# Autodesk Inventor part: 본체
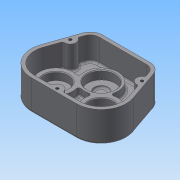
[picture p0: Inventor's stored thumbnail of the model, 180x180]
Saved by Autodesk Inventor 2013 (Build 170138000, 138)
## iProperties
Created: 2014-12
Part Number: 본체
Material: 일반
Document SubType Name: Modeling
Designer: Administrator
Density: 1 g/cm^3
Author: Administrator
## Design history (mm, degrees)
sketch "스케치1"
  geometry: L1 (0, 0)-(-32.527, -32.527); L2 (0, 0)-(32.527, -32.527); L3 (0, 0)-(0, -46); L4 (-47, 36)-(47, 36); L5 (-32.527, -68.527)-(32.527, -68.527); L6 (-66.565, -20.803)-(-47, 36); L7 (66.565, -20.803)-(47, 36); A1 r 46 centre (0, 0) between (-32.527, -32.527) and (0, -46); A2 r 36 centre (32.527, -32.527) between (32.527, -68.527) and (66.565, -20.803); A3 r 36 centre (32.527, -32.527) between (-0.86, -45.992) and (0, -47.954); A4 r 36 centre (-32.527, -32.527) between (0, -47.954) and (0.86, -45.992); A5 r 36 centre (-32.527, -32.527) between (-66.565, -20.803) and (-32.527, -68.527); 3 further points
  constraints: 14 end point, 13 point on circle, 5 centre point, 3 coincident, 2 midpoint, 2 tangent, 2 vertical alignment, 1 parallel, 1 perpendicular, 1 vertical
  dimensions: "d2" = 92 diameter of A1; "d3" = 45 deg angle of L3 L1; "d5" = 45 deg angle of L2 L3; "d9" = 36 distance from line of L4 point (0, 0); "d10" = 94 distance of L4.start L4.end; "d11" = 36 distance from line of L1.end L5; "d12" = 36 radius of A5; "d13" = 36 radius of A2
extrude "돌출1" new body sketch "스케치1" distance "d14" = 44; taper "d15" = 0 deg
fillet "모깎기1" dims "d16" = 18
sketch "스케치2"
  geometry: L1 (46.453, 22.233)-(61.837, -22.432) reference; L2 (32.527, -63.527)-(-32.527, -63.527) reference; L3 (-61.837, -22.432)-(-46.453, 22.233) reference; L4 (34.162, 36)-(-34.162, 36) reference; L5 (-51.181, 23.862)-(-66.565, -20.803) reference; L6 (-32.527, -68.527)-(32.527, -68.527) reference; L7 (66.565, -20.803)-(51.181, 23.862) reference; L8 (-49.095, 14.564)-(-53.822, 16.192); L9 (-54.305, -0.564)-(-59.033, 1.064); L10 (49.095, 14.564)-(53.822, 16.192); L11 (54.305, -0.564)-(59.033, 1.064); L12 (-8, -63.527)-(-8, -68.527); L13 (8, -63.527)-(8, -68.527); A1 r 8 centre (-51.7, 7) between (-54.305, -0.564) and (-49.095, 14.564); A2 r 8 centre (51.7, 7) between (49.095, 14.564) and (54.305, -0.564); A3 r 8 centre (0, -63.527) between (8, -63.527) and (-8, -63.527); 1 further point
  constraints: 12 end point, 11 point on line, 6 point on circle, 6 tangent, 5 perpendicular, 3 centre point, 1 midpoint, 1 parallel
  dimensions: "d18" = 16 diameter of A1; "d19" = 16 diameter of A2; "d20" = 16 diameter of A3; "d21" = 29 distance from line of L4 A1.centre; "d22" = 29 distance from line of L4 A2.centre
extrude "돌출2" join sketch "스케치2" stored distance "d23" = 0; taper "d24" = 0 deg
extrude "돌출3" join sketch "스케치2" stored distance "d25" = 0; taper "d26" = 0 deg
sketch "스케치6"
  geometry: C1 r 20 at (-32.527, -32.527); C2 r 20 at (32.527, -32.527); A1 r 36 centre (32.527, -32.527) between (32.527, -68.527) and (66.565, -20.803) reference; A2 r 36 centre (-32.527, -32.527) between (-66.565, -20.803) and (-32.527, -68.527) reference; 1 further point
  constraints: 2 centre point, 2 coincident
  dimensions: "d41" = 40 diameter of C1; "d42" = 40 diameter of C2
extrude "돌출7" join sketch "스케치6" distance "d43" = 7; taper "d44" = -10 deg
sketch "스케치7"
  geometry: C1 r 18.766 at (0, 0) reference; C2 r 18.766 at (65.054, 0) reference; C3 r 15 at (0, 0); C4 r 15 at (65.054, 0); 1 further point
  constraints: 2 centre point, 2 coincident
  dimensions: "d45" = 30 diameter of C3; "d46" = 30 diameter of C4
extrude "돌출8" cut sketch "스케치7" distance "d47" = 7; taper "d48" = 0 deg
sketch "스케치8"
  geometry: L1 (-1.635, 68.527)-(66.689, 68.527) reference; L2 (83.708, 56.389)-(99.091, 11.723) reference; L3 (65.054, -36)-(0, -36) reference; L4 (-34.038, 11.723)-(-18.654, 56.389) reference; C1 r 15 at (0, 0) reference; C2 r 15 at (65.054, 0) reference; C3 r 20 at (0, 0) reference; C4 r 20 at (65.054, 0) reference; C5 r 7.75 at (0, 0); C6 r 7.75 at (65.054, 0); A1 r 18 centre (-1.635, 50.527) between (-1.635, 68.527) and (-18.654, 56.389) reference; A2 r 18 centre (66.689, 50.527) between (83.708, 56.389) and (66.689, 68.527) reference; A3 r 36 centre (65.054, 0) between (65.054, -36) and (99.091, 11.723) reference; A4 r 36 centre (0, 0) between (-34.038, 11.723) and (0, -36) reference; 1 further point
  constraints: 2 centre point, 2 coincident
  dimensions: "d49" = 15.5 diameter of C5; "d50" = 15.5 diameter of C6
extrude "돌출9" cut sketch "스케치8" stored distance "d51" = 7; taper "d52" = 0 deg
fillet "모깎기3" dims "d81" = 3
fillet "모깎기4" dims "d82" = 3
fillet "모깎기6" dims "d87" = 0.1
sketch "스케치9"
  geometry: L1 (34.162, 36)-(-34.162, 36) reference; 2 further points
  constraints: 1 vertical alignment, 1 other
  dimensions: "d88" = 30 distance from line of L1 point (0, 6)
feature "엠보싱1" sketch "스케치9" dims "d2" = 92, "d89" = 1, "d90" = 0
chamfer "모따기3" distance "d94" = 1; stored, may be unused: second distance "d95" = 2, angle "d96" = 45 deg
sketch "스케치10"
  geometry: L1 (-32.527, -68.527)-(32.527, -68.527) reference; L2 (34.162, 36)-(-34.162, 36) reference; L3 (-34.162, 31)-(34.162, 31); L4 (-32.527, -63.527)-(32.527, -63.527); L5 (-46.453, 22.233)-(-61.837, -22.432); L6 (46.453, 22.233)-(61.837, -22.432); C1 r 7.75 at (32.527, -32.527) reference; C2 r 7.75 at (-32.527, -32.527) reference; A1 r 36 centre (32.527, -32.527) between (32.527, -68.527) and (66.565, -20.803) reference; A2 r 18 centre (34.162, 18) between (51.181, 23.862) and (34.162, 36) reference; A3 r 18 centre (-34.162, 18) between (-34.162, 36) and (-51.181, 23.862) reference; A4 r 36 centre (-32.527, -32.527) between (-66.565, -20.803) and (-32.527, -68.527) reference; A5 r 31 centre (-32.527, -32.527) between (-61.837, -22.432) and (-32.527, -63.527); A6 r 31 centre (32.527, -32.527) between (32.527, -63.527) and (61.837, -22.432); A7 r 13 centre (-34.162, 18) between (-34.162, 31) and (-46.453, 22.233); A8 r 13 centre (34.162, 18) between (46.453, 22.233) and (34.162, 31); 1 further point
  constraints: 8 end point, 8 point on circle, 4 centre point, 4 coincident, 4 tangent, 2 parallel
  dimensions: "d98" = 5 distance between parallel lines of L2 L3; "d99" = 5 radial gap between concentric circles of A3 A7; "d100" = 5 radial gap between concentric circles of A2 A8; "d101" = 5 radial gap between concentric circles of A4 A5; "d102" = 5 radial gap between concentric circles of A1 A6; "d103" = 5 distance between parallel lines of L1 L4
extrude "돌출10" cut sketch "스케치10" distance "d104" = 34; taper "d105" = 0 deg
sketch "스케치11"
  geometry: C1 r 7.75 at (-32.527, -32.527) reference; C2 r 7.75 at (32.527, -32.527) reference; A1 r 31 centre (-32.527, -32.527) between (-61.837, -22.432) and (-32.527, -63.527) reference; A2 r 31 centre (32.527, -32.527) between (32.527, -63.527) and (61.837, -22.432) reference; A3 r 24 centre (-32.527, -32.527) between (-21.111, -11.416) and (-11.416, -21.111); A4 r 24 centre (32.527, -32.527) between (11.416, -21.111) and (21.111, -11.416); A5 r 24 centre (0, 0) between (-11.416, -21.111) and (11.416, -21.111); A6 r 24 centre (0, 0) between (21.111, -11.416) and (-21.111, -11.416); 1 further point
  constraints: 8 point on circle, 4 centre point, 3 coincident, 1 concentric
  dimensions: "d107" = 48 diameter of A3; "d108" = 48 diameter of A4; "d109" = 24 radius of A6
extrude "돌출11" join sketch "스케치11" distance "d110" = 11; taper "d111" = 0 deg
sketch "스케치12"
  geometry: C1 r 20 at (0, 0); C2 r 17.5 at (-32.527, -32.527); C3 r 17.5 at (32.527, -32.527); A1 r 24 centre (-32.527, -32.527) between (-21.111, -11.416) and (-11.416, -21.111) reference; A2 r 24 centre (32.527, -32.527) between (11.416, -21.111) and (21.111, -11.416) reference; A3 r 24 centre (0, 0) between (21.111, -11.416) and (-21.111, -11.416) reference
  constraints: 3 centre point, 3 coincident
  dimensions: "d112" = 40 diameter of C1; "d113" = 35 diameter of C2; "d114" = 35 diameter of C3
extrude "돌출12" cut sketch "스케치12" distance "d115" = 11; taper "d116" = 0 deg
sketch "스케치13"
  geometry: C1 r 20 at (0, 0) reference; C2 r 10 at (0, 0)
  constraints: 1 centre point, 1 coincident
  dimensions: "d117" = 20 diameter of C2
extrude "돌출13" cut sketch "스케치13" distance "d118" = 3; taper "d119" = 0 deg
sketch "스케치14"
  geometry: L1 (32.527, -63.527)-(-32.527, -63.527) reference; L2 (-61.837, -22.432)-(-46.453, 22.233) reference; L3 (-32.527, -68.527)-(32.527, -68.527) reference; L4 (34.162, 36)-(-34.162, 36) reference; L5 (-51.181, 23.862)-(-66.565, -20.803) reference; L6 (-8, -63.527)-(-8, -68.527); L7 (8, -63.527)-(8, -68.527); L8 (-49.095, 14.564)-(-53.822, 16.192); L9 (-54.305, -0.564)-(-59.033, 1.064); A1 r 8 centre (-51.7, 7) between (-54.305, -0.564) and (-49.095, 14.564); A2 r 8 centre (0, -63.527) between (8, -63.527) and (-8, -63.527); 1 further point
  constraints: 8 end point, 5 point on line, 4 point on circle, 4 tangent, 2 centre point, 2 parallel, 2 perpendicular, 1 midpoint
  dimensions: "d120" = 16 diameter of A1; "d122" = 16 diameter of A2; "d123" = 29 distance from line of L4 A1.centre
extrude "돌출14" join sketch "스케치14" stored distance "d124" = 0; taper "d125" = 0 deg
extrude "돌출15" join sketch "스케치14" stored distance "d126" = 0; taper "d127" = 0 deg
hole "구멍4" diameter "d130" = 4.134; stored, may be unused: countersink angle "d134" = 90 deg, drill point angle "d136" = 118 deg; dims "d128" = 10, "d129" = 10, "d131" = 20, "d132" = 4, "d133" = 2, "d135" = 23
hole "구멍5" diameter "d139" = 4.134; stored, may be unused: countersink angle "d143" = 90 deg, drill point angle "d145" = 118 deg; dims "d137" = 10, "d138" = 10, "d140" = 20, "d141" = 4, "d142" = 2, "d144" = 23
fillet "모깎기7" dims "d146" = 3
fillet "모깎기8" dims "d147" = 3
chamfer "모따기4" distance "d148" = 1; stored, may be unused: second distance "d149" = 2, angle "d150" = 45 deg
fillet "모깎기9" dims "d151" = 0.3
sketch "스케치15"
  geometry: C1 r 20 at (0, 0) reference; C2 r 20 at (0, 0)
  constraints: 1 centre point, 1 coincident
  dimensions: "d153" = 40 diameter of C2
extrude "돌출16" cut sketch "스케치15" distance "d154" = 1; taper "d155" = 0 deg
fillet "모깎기11" dims "d156" = 0.3
sketch "스케치16"
  geometry: C1 r 10 at (0, 0) reference; C2 r 10 at (0, 0)
  constraints: 1 centre point, 1 coincident
  dimensions: "d157" = 20 diameter of C2
extrude "돌출17" join sketch "스케치16" stored distance "d158" = 1; taper "d159" = 0 deg
sketch "스케치17"
  geometry: C1 r 19.7 at (0, 0) reference; C2 r 10 at (0, 0)
  constraints: 1 centre point, 1 coincident
  dimensions: "d160" = 20 diameter of C2
extrude "돌출18" cut sketch "스케치17" distance "d161" = 3; taper "d162" = 0 deg
fillet "모깎기12" dims "d163" = 3
node "솔리드1"
mirror "대칭1"
mirror "대칭2"
node "절단 모서리 투영1"
node "절단 모서리 투영2"
other parameters: "d7" = 72, "d8" = 72, "d27" = 48, "d106" = 48
